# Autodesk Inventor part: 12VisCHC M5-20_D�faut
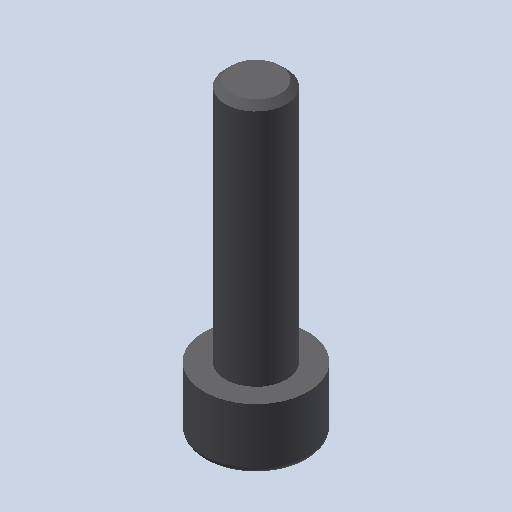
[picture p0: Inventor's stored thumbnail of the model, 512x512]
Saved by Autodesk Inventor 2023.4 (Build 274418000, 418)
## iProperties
Created: 2011-01
Part Number: 12VisCHC M5-20_D�faut
Document SubType Name: Modeling
Designer: eric
Density: 1 g/cm^3
Mass: 0.638556 g
Surface Area: 5.8504 cm^2
Volume: 0.638556 cm^3
Material: Générique
Appearance: Red
Author: eric
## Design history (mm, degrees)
feature "Base1"
node "Corps solides"
node "Corps surfaciques"
node "Solide1"
